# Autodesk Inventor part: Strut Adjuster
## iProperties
Shininess: 64.0
Length Units: 11272
Angle Units: 11279
Time Units: 11290
Mass Units: 11283
Length Display Precision: 3
Angle Display Precision: 2
Compacted: True
Part Number: Strut Adjuster
Document SubType Name: Modeling
Created: 2005-03
Designer: Admin
Manufacturer: Standard
Standards Organization: Custom
Density: 1 g/cm^3
Density: 0.0
Volumn: 0.0
Area: 0.0
PropertySet Name: Model Information
Control State: 0
Master: False
Checked Out: False
Author: Admin
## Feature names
1. ExtrusionBlind1
2. ExtrusionBlind2
3. ExtrusionBlind3
4. Chamfer1
5. Hole1
6. Fillet1
